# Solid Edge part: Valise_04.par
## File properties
Author: Bernard DUMAS
Template: Normal.par
Last saved by: FR026244
Revision: 11
Application: Solid Edge
Material: Bois, Frêne
Style de face: Jaune kaki
Style de remplissage: Liège
Style virtuel: Frêne verni
Coef. of Thermal Exp: 0.0
Thermal Conductivity: 0.0
Specific Heat: 0.0
Modulus of Elasticity: 0.0
Poission's Ratio: 0.0
Yield Stress: 0.0
Ultimate Stress: 0.0
Elongation: 0.0
Densité: 460.000 kg/m^3
Précision: 0.9900
Document Number: 04
Revision: a
Project Name: Slamson
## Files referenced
..\Valise_Salmson.asm
bD:\Documents and Settings\FR026244\Mes Documents\Bernard\Slamson\Valise-Salmson\Valise_Salmson.asm
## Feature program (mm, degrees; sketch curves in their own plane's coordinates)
sketch for "unnamed Protrusion 1" plane through (0, 0, 0) normal (0, -1, 0) x-axis (1, 0, 0)
extrude "unnamed Protrusion 1" add to key point symmetric
extrude "unnamed Cutout 1" cut finite 6
extrude "Enlèvement_matière_2" cut finite 6
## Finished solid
Body 1: solid body, 10 faces, 24 edges, 16 vertices.
  Faces by surface: plane 10
  Edges by curve: line 24
Bounding box of the edges (mm): 6.000 x 850.000 x 54.000, from (0, -425, 106) to (6, 425, 160).
Planar faces by outward normal: +x 2, +y 2, +z 2, -x 1, -y 2, -z 1
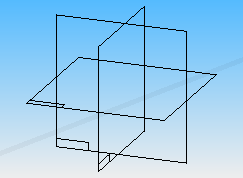
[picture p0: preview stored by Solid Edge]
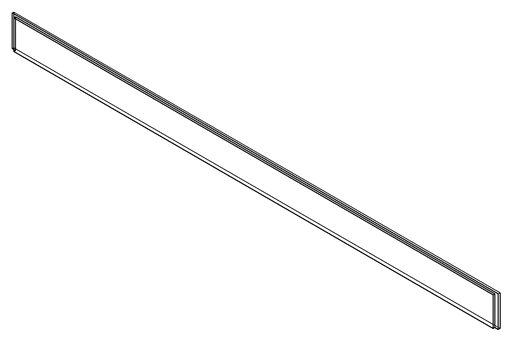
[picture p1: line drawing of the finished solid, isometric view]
